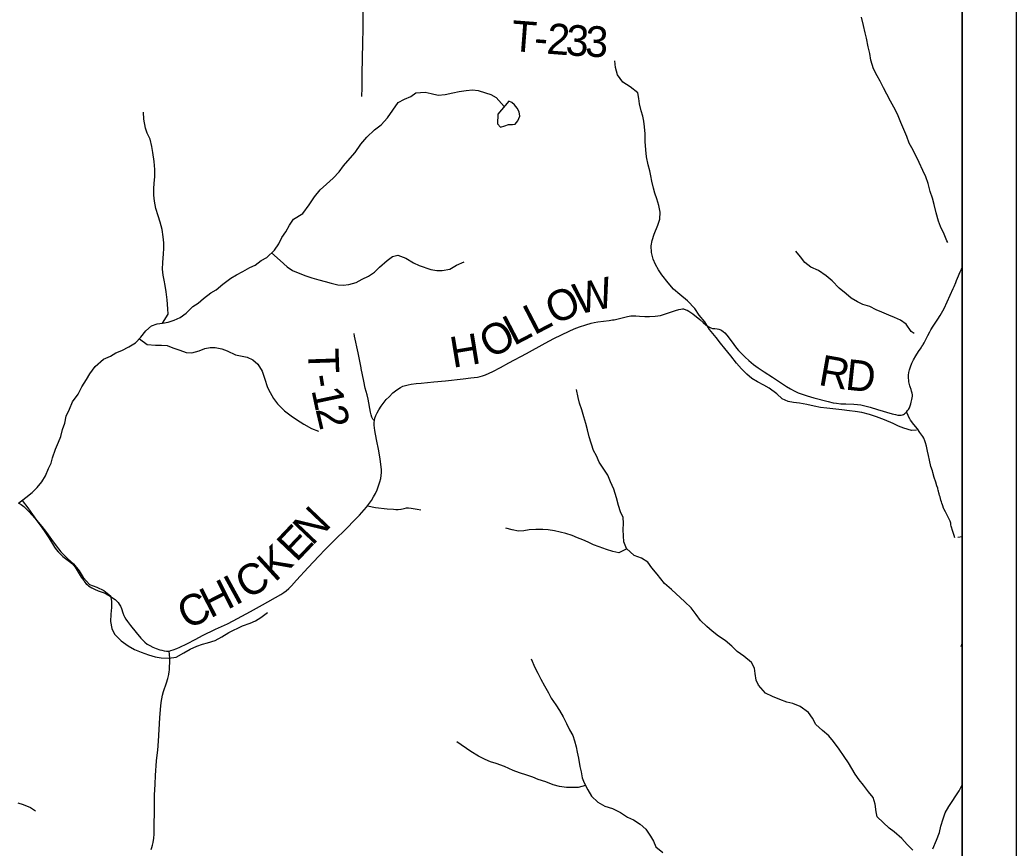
# Model space of a CAD drawing. Extents: x 0 to 34, y 0 to 22.
# Drawn here: x 7.37 to 9.214, y 18.618 to 20.151 of the extents above; entities that cross this region are included whole.
import ezdxf

# ---------------------------------------------------------------- set-up
doc = ezdxf.new("R2010")
doc.units = 0
for name, color, linetype in [('Default', 7, 'Continuous'), ('GM_X_County_Road', 7, 'Continuous'), ('GM_X_County_Road_Text', 7, 'Continuous'), ('GM_X_Minor_Lake', 7, 'Continuous'), ('GM_X_Minor_River', 7, 'Continuous'), ('GM_X_Township_Road', 7, 'Continuous'), ('GM_X_Township_Road_Text', 7, 'Continuous'), ('SH_Cut_Line', 7, 'Continuous'), ('SH_Data', 7, 'Continuous')]:
    doc.layers.add(name, color=color, linetype=linetype)

msp = doc.modelspace()

# ---------------------------------------------------------------- linework, layer by layer
at = {"layer": 'Default'}
msp.add_lwpolyline([(9.1142, 17.7402), (9.1142, 20.5497), (8.8095, 20.7701), (8.7304, 20.823), (8.6734, 20.858), (8.6167, 20.8996), (2.3571, 20.8996)], dxfattribs=at)
at = {"layer": 'GM_X_County_Road'}
for points in [[(9.0115, 19.4251), (9.0134, 19.4277), (9.0153, 19.43), (9.0169, 19.4329), (9.0184, 19.4365), (9.0194, 19.4402), (9.0203, 19.4434), (9.0214, 19.448), (9.022, 19.4516), (9.0224, 19.4546), (9.0224, 19.4571), (9.0219, 19.4602), (9.0208, 19.4637), (9.0197, 19.4666), (9.0184, 19.4715), (9.0176, 19.4738), (9.0163, 19.4786), (9.0159, 19.4811), (9.0158, 19.4817), (9.0155, 19.4835), (9.0151, 19.4885), (9.0152, 19.4934), (9.0158, 19.4983), (9.0169, 19.5031), (9.0188, 19.5089), (9.0213, 19.5152), (9.0246, 19.5219), (9.0285, 19.529), (9.0335, 19.5368), (9.0384, 19.544), (9.0394, 19.5455), (9.04, 19.5466), (9.0413, 19.5487), (9.0422, 19.5503), (9.0438, 19.553), (9.0507, 19.5669), (9.0543, 19.5734), (9.0565, 19.5772), (9.0608, 19.584), (9.0694, 19.597), (9.0737, 19.6038), (9.0762, 19.6081), (9.0808, 19.6169), (9.0867, 19.6292), (9.0979, 19.6535), (9.0995, 19.6575), (9.1026, 19.665), (9.104, 19.6684), (9.1056, 19.6725), (9.1105, 19.6845), (9.1129, 19.6895), (9.1137, 19.6912), (9.1142, 19.6923)], [(8.2051, 19.4882), (8.2169, 19.4897), (8.2218, 19.4906), (8.2266, 19.4919), (8.2318, 19.4937), (8.2387, 19.4967), (8.2454, 19.5), (8.2596, 19.5075), (8.2754, 19.5161), (8.3077, 19.5335), (8.3425, 19.5526), (8.3584, 19.5611), (8.3869, 19.575), (8.396, 19.579), (8.4059, 19.5827), (8.4176, 19.5866), (8.4277, 19.5896), (8.4332, 19.5909), (8.4399, 19.5919), (8.4608, 19.5944), (8.4669, 19.5954), (8.47, 19.596), (8.4851, 19.5995), (8.4902, 19.6009), (8.4925, 19.6015), (8.4949, 19.602), (8.4981, 19.6025), (8.5008, 19.6029), (8.5101, 19.6031), (8.5171, 19.6026), (8.5269, 19.602), (8.5356, 19.6019), (8.5461, 19.6023), (8.551, 19.6028), (8.5558, 19.6038), (8.5618, 19.6055), (8.5835, 19.613), (8.59, 19.615), (8.5936, 19.6157), (8.5967, 19.6159), (8.5986, 19.6158), (8.6026, 19.6145), (8.6054, 19.6133), (8.6086, 19.6115), (8.6157, 19.6065), (8.6288, 19.5961), (8.635, 19.5909), (8.64, 19.5864), (8.6439, 19.5834), (8.6466, 19.5819), (8.6494, 19.5806), (8.6524, 19.5798), (8.6567, 19.5795), (8.661, 19.5792), (8.664, 19.5786), (8.6675, 19.5772), (8.6696, 19.5761), (8.6721, 19.5742), (8.6749, 19.5717), (8.6786, 19.5675), (8.6865, 19.5571), (8.6968, 19.5431), (8.7004, 19.5388), (8.7063, 19.5325), (8.7125, 19.5264), (8.7195, 19.5202), (8.7282, 19.5132), (8.7366, 19.5069), (8.7479, 19.4992), (8.7631, 19.4894), (8.7891, 19.4724), (8.7965, 19.468), (8.8037, 19.4642), (8.811, 19.4609), (8.8185, 19.4579), (8.8274, 19.455), (8.8399, 19.4515), (8.8664, 19.4445), (8.8754, 19.4424), (8.882, 19.4413), (8.89, 19.4405), (8.8992, 19.4401), (8.914, 19.4396), (8.9207, 19.439), (8.9268, 19.4382), (8.9341, 19.4367), (8.9443, 19.4341), (8.9579, 19.43), (8.9846, 19.4217), (8.9907, 19.4202), (8.9956, 19.4193), (8.9993, 19.419), (9.0017, 19.4192), (9.0041, 19.4197), (9.0058, 19.4204), (9.0078, 19.4218), (9.0098, 19.4233), (9.0115, 19.4251)], [(8.0263, 19.409), (8.0274, 19.4138), (8.029, 19.4185), (8.0313, 19.4236), (8.0343, 19.429), (8.0388, 19.4358), (8.0443, 19.4433), (8.0482, 19.4481), (8.0534, 19.4535), (8.0605, 19.4603), (8.0653, 19.4644), (8.0698, 19.4676), (8.0746, 19.4705), (8.079, 19.4727), (8.0837, 19.4744), (8.0885, 19.4757), (8.0946, 19.4768), (8.1039, 19.4778), (8.1126, 19.4786), (8.1361, 19.4808), (8.1577, 19.4828), (8.1904, 19.4864), (8.2051, 19.4882)], [(8.0136, 19.2512), (8.0209, 19.2616), (8.0247, 19.2679), (8.0282, 19.2745), (8.0313, 19.2813), (8.034, 19.2883), (8.0364, 19.296), (8.0379, 19.302), (8.0389, 19.3075), (8.0394, 19.3131), (8.0395, 19.318), (8.0391, 19.3236), (8.0372, 19.3378), (8.0345, 19.3531), (8.0303, 19.3744), (8.0271, 19.3911), (8.0263, 19.3961), (8.026, 19.4007), (8.0258, 19.4037), (8.026, 19.4065), (8.0263, 19.409)], [(7.3666, 19.2573), (7.3721, 19.2541), (7.3772, 19.2504), (7.3819, 19.2462), (7.3852, 19.2425), (7.3872, 19.2401), (7.3974, 19.2285), (7.4052, 19.2189), (7.4108, 19.2115), (7.4174, 19.2018), (7.4234, 19.1924), (7.434, 19.1749), (7.4371, 19.1704), (7.4407, 19.1662), (7.445, 19.1619), (7.4496, 19.1579), (7.4618, 19.1485), (7.4671, 19.144), (7.4697, 19.1412), (7.4724, 19.1377), (7.4835, 19.1197), (7.4881, 19.1132), (7.4898, 19.1109), (7.4929, 19.1074), (7.4949, 19.1055), (7.4973, 19.1036), (7.5032, 19.0996), (7.5084, 19.097), (7.5148, 19.0942), (7.5259, 19.0903), (7.5299, 19.0885), (7.537, 19.0845), (7.5417, 19.0814), (7.5463, 19.0781), (7.5491, 19.0756), (7.5517, 19.0728), (7.554, 19.0697), (7.5561, 19.0658), (7.5582, 19.0612), (7.5608, 19.0535), (7.5627, 19.0483), (7.5637, 19.0461), (7.566, 19.0418), (7.5691, 19.0373), (7.5748, 19.03), (7.5853, 19.0169), (7.5939, 19.0064), (7.5973, 19.0028), (7.6014, 18.9991), (7.6058, 18.9958), (7.6105, 18.9929), (7.6159, 18.9901), (7.6221, 18.9875), (7.6291, 18.9851), (7.6327, 18.9841), (7.6371, 18.9832), (7.6412, 18.9826), (7.6441, 18.9825), (7.6464, 18.9827)], [(7.6464, 18.9827), (7.6494, 18.9836), (7.6537, 18.9852), (7.6604, 18.9877), (7.6662, 18.9899), (7.679, 18.9961), (7.6956, 19.0047), (7.7083, 19.0113), (7.7322, 19.023), (7.7542, 19.0333), (7.7647, 19.0386), (7.7969, 19.0558), (7.8191, 19.0683), (7.853, 19.0876), (7.8588, 19.0913), (7.8628, 19.0942), (7.8679, 19.0987), (7.8726, 19.1036), (7.8818, 19.1137), (7.9037, 19.1374), (7.9232, 19.1583), (7.9353, 19.1707), (7.9493, 19.1847), (7.9773, 19.2121), (7.9872, 19.2223), (7.9987, 19.2345), (8.0119, 19.2493), (8.0136, 19.2512)]]:
    msp.add_lwpolyline(points, dxfattribs=at)
at = {"layer": 'GM_X_Minor_Lake'}
for points in [[(8.2545, 19.9763), (8.2543, 19.9585), (8.2599, 19.9523), (8.2675, 19.9545), (8.2743, 19.9571), (8.2819, 19.9574), (8.2872, 19.958), (8.2919, 19.9637), (8.2954, 19.9727), (8.294, 19.9803), (8.2903, 19.9872), (8.2858, 19.9933), (8.2805, 19.998), (8.2753, 20.0003)], [(8.2753, 20.0003), (8.2545, 19.9763)]]:
    msp.add_lwpolyline(points, dxfattribs=at)
at = {"layer": 'GM_X_Minor_River'}
for p, q in [((9.1065, 19.1932), (9.1142, 19.1945)), ((9.1125, 18.991), (9.1142, 18.9968))]:
    msp.add_line(p, q, dxfattribs=at)
for points in [[(9.088, 19.7388), (9.086, 19.7419), (9.0808, 19.7541), (9.0746, 19.7686), (9.0705, 19.7781), (9.0665, 19.7934), (9.0626, 19.809), (9.0593, 19.8208), (9.0553, 19.833), (9.0513, 19.8478), (9.0469, 19.8604), (9.0414, 19.8722), (9.0347, 19.8867), (9.0236, 19.9096), (9.0166, 19.9226), (9.0122, 19.9348), (9.0063, 19.9481), (9.0008, 19.9611), (8.9949, 19.976), (8.9879, 19.989), (8.9816, 20.0004), (8.9749, 20.0134), (8.9686, 20.0249), (8.9627, 20.0371), (8.9568, 20.0474), (8.9505, 20.0604), (8.9454, 20.0764), (8.9433, 20.0885), (8.9404, 20.1011), (8.9372, 20.1167), (8.9346, 20.1269), (8.9318, 20.1403), (8.9278, 20.1559)], [(9.0299, 19.3915), (9.0205, 19.3908), (9.0065, 19.3952), (8.9967, 19.3991), (8.9869, 19.4038), (8.9707, 19.4108), (8.9556, 19.4163), (8.9428, 19.4207), (8.9284, 19.4243), (8.9163, 19.4263), (8.9057, 19.4276), (8.8917, 19.4289), (8.8751, 19.4307), (8.8637, 19.432), (8.8523, 19.4336), (8.8402, 19.4361), (8.827, 19.4389), (8.813, 19.4417), (8.8024, 19.443), (8.7926, 19.4447), (8.7809, 19.4494), (8.7711, 19.4586), (8.7573, 19.469), (8.7475, 19.4745), (8.7354, 19.4811), (8.7253, 19.4869), (8.7155, 19.4954), (8.7061, 19.505), (8.6964, 19.5157), (8.6864, 19.5291), (8.6748, 19.5426), (8.6669, 19.5525), (8.6591, 19.5629), (8.6468, 19.5778), (8.6379, 19.592), (8.6278, 19.6046), (8.6192, 19.6165), (8.6061, 19.6311), (8.5919, 19.6423), (8.5799, 19.6527), (8.5701, 19.6642), (8.5582, 19.6787), (8.5523, 19.6883), (8.5467, 19.6979), (8.5423, 19.7082), (8.539, 19.72), (8.5388, 19.7328), (8.5404, 19.7427), (8.5444, 19.7544), (8.551, 19.771), (8.5546, 19.7819), (8.5551, 19.7952), (8.5526, 19.807), (8.549, 19.8199), (8.5457, 19.8298), (8.5432, 19.8394), (8.5399, 19.8523), (8.5381, 19.8622), (8.536, 19.8717), (8.5331, 19.8827), (8.5303, 19.8976), (8.5285, 19.9101), (8.5276, 19.9257), (8.5274, 19.9397), (8.5264, 19.953), (8.525, 19.9632), (8.5232, 19.9727), (8.5203, 19.9823), (8.5171, 19.9956), (8.5161, 20.0054), (8.5139, 20.0157), (8.4997, 20.0269), (8.4865, 20.0358), (8.4764, 20.0488), (8.4724, 20.0629), (8.4711, 20.0747)], [(7.6343, 19.5898), (7.6445, 19.5912), (7.6556, 19.5948), (7.6666, 19.6), (7.6777, 19.6082), (7.6904, 19.6201), (7.7003, 19.6268), (7.7099, 19.635), (7.7233, 19.6455), (7.7336, 19.6514), (7.7459, 19.6619), (7.7605, 19.673), (7.7708, 19.679), (7.7826, 19.6849), (7.7956, 19.6927), (7.8055, 19.6971), (7.8166, 19.7053), (7.8269, 19.7108), (7.8411, 19.7247), (7.8496, 19.7363), (7.855, 19.748), (7.8624, 19.7585), (7.8694, 19.7709), (7.8767, 19.7822), (7.8935, 19.7926), (7.9055, 19.8084), (7.9151, 19.8234), (7.9259, 19.8362), (7.9378, 19.8466), (7.9497, 19.8579), (7.9612, 19.8698), (7.9689, 19.8804), (7.977, 19.8901), (7.9905, 19.9051), (8.0013, 19.9205), (8.0124, 19.9336), (8.0263, 19.9471), (8.0389, 19.9568), (8.0504, 19.9695), (8.0605, 19.9834), (8.0705, 19.9981), (8.0823, 20.004), (8.0938, 20.0088), (8.1033, 20.0159), (8.1204, 20.0168), (8.1314, 20.0143), (8.1442, 20.0115), (8.1571, 20.0125), (8.1716, 20.0157), (8.1834, 20.0182), (8.1963, 20.0203), (8.2077, 20.0213), (8.2186, 20.02), (8.2319, 20.016), (8.2417, 20.0125), (8.2515, 20.0071), (8.2667, 19.9904)], [(7.6343, 19.5898), (7.6447, 19.6063), (7.6437, 19.6162), (7.6424, 19.6329), (7.6407, 19.6473), (7.639, 19.6591), (7.6368, 19.669), (7.635, 19.6785), (7.634, 19.6895), (7.6346, 19.7017), (7.6359, 19.7176), (7.6364, 19.7278), (7.6362, 19.7384), (7.6352, 19.7494), (7.6334, 19.7627), (7.6298, 19.7764), (7.6258, 19.7882), (7.6214, 19.802), (7.6189, 19.8153), (7.6179, 19.8266), (7.6181, 19.8384), (7.6186, 19.8483), (7.6199, 19.8604), (7.6201, 19.874), (7.6187, 19.8888), (7.6159, 19.9052), (7.6142, 19.9166), (7.6109, 19.9299), (7.6054, 19.941), (7.6025, 19.9505), (7.5993, 19.9672), (7.5987, 19.9801)], [(7.8359, 19.7196), (7.8519, 19.7056), (7.8646, 19.694), (7.8747, 19.6871), (7.8883, 19.6816), (7.8996, 19.6772), (7.9102, 19.6737), (7.9234, 19.6697), (7.9352, 19.6669), (7.9461, 19.6634), (7.9586, 19.6605), (7.9684, 19.66), (7.9787, 19.661), (7.9924, 19.665), (8.0038, 19.6709), (8.0153, 19.6768), (8.0264, 19.6839), (8.0359, 19.6929), (8.0501, 19.7052), (8.0601, 19.7127), (8.0696, 19.7152), (8.0843, 19.7101), (8.0986, 19.7011), (8.1092, 19.6965), (8.1307, 19.689), (8.1416, 19.6869), (8.1515, 19.6872), (8.1659, 19.6896), (8.1782, 19.6971), (8.1923, 19.7033)], [(9.0254, 19.5707), (9.0198, 19.5744), (9.0105, 19.5874), (9, 19.5951), (8.9894, 19.6002), (8.9785, 19.6045), (8.966, 19.61), (8.9555, 19.6143), (8.9434, 19.6202), (8.9306, 19.6241), (8.9204, 19.6292), (8.9091, 19.6358), (8.8994, 19.6435), (8.887, 19.6543), (8.8739, 19.6681), (8.8626, 19.677), (8.8483, 19.6867), (8.8344, 19.6929), (8.8231, 19.7018), (8.8149, 19.7121), (8.8063, 19.7225)], [(7.3677, 19.2562), (7.3811, 19.2667), (7.3926, 19.2764), (7.4022, 19.2853), (7.4107, 19.2958), (7.4177, 19.3067), (7.4231, 19.3203), (7.4278, 19.3305), (7.4306, 19.3403), (7.4361, 19.3566), (7.4416, 19.369), (7.4455, 19.3799), (7.4491, 19.3928), (7.453, 19.4045), (7.4558, 19.4177), (7.4621, 19.4305), (7.4672, 19.4437), (7.478, 19.4584), (7.4849, 19.4716), (7.4935, 19.4851), (7.4997, 19.496), (7.5093, 19.5092), (7.525, 19.523), (7.5376, 19.5285), (7.5479, 19.5344), (7.5586, 19.5388), (7.5716, 19.5455), (7.5838, 19.5533), (7.5938, 19.5634), (7.6034, 19.5754), (7.6134, 19.5844), (7.624, 19.588), (7.6343, 19.5898)], [(7.5912, 19.5607), (7.6057, 19.5503), (7.6209, 19.549), (7.6319, 19.5489), (7.6425, 19.548), (7.6534, 19.544), (7.6659, 19.5393), (7.6776, 19.5353), (7.6882, 19.5344), (7.7019, 19.5384), (7.7122, 19.5425), (7.7221, 19.5446), (7.7315, 19.5445), (7.744, 19.542), (7.7538, 19.5385), (7.7689, 19.5307), (7.7787, 19.5291), (7.7905, 19.5266), (7.801, 19.5219), (7.8108, 19.5138), (7.8186, 19.5005), (7.8229, 19.4875), (7.8284, 19.4707), (7.8336, 19.4612), (7.8395, 19.4501), (7.8466, 19.4405), (7.8601, 19.4271), (7.8721, 19.4178), (7.8819, 19.4112), (7.8958, 19.4027), (7.9101, 19.3949), (7.9226, 19.3899)], [(9.0229, 18.6145), (9.0124, 18.6249), (9.003, 18.6356), (8.9888, 18.6483), (8.979, 18.6553), (8.9682, 18.6653), (8.9573, 18.676), (8.9551, 18.6855), (8.9534, 18.6992), (8.9498, 18.7118), (8.9412, 18.7221), (8.9315, 18.7348), (8.9237, 18.7447), (8.9162, 18.7547), (8.904, 18.7757), (8.8961, 18.7876), (8.8865, 18.801), (8.876, 18.8155), (8.8678, 18.8259), (8.8558, 18.8355), (8.8434, 18.8471), (8.8375, 18.8585), (8.8301, 18.8692), (8.8143, 18.8804), (8.8007, 18.8855), (8.7897, 18.8883), (8.7769, 18.8934), (8.7633, 18.8986), (8.7501, 18.9048), (8.7374, 18.9194), (8.733, 18.9289), (8.7309, 18.9415), (8.7299, 18.951), (8.7247, 18.9613), (8.7104, 18.9732), (8.698, 18.9821), (8.6879, 18.9921), (8.6755, 19.0021), (8.6635, 19.0106), (8.6519, 19.0195), (8.6418, 19.0284), (8.6301, 19.0391), (8.6219, 19.0502), (8.6126, 19.0625), (8.601, 19.0736), (8.5766, 19.0967), (8.5635, 19.1075), (8.5497, 19.1251), (8.54, 19.137), (8.5325, 19.1474), (8.5205, 19.1544), (8.5073, 19.1595), (8.4927, 19.1725), (8.4879, 19.1847), (8.4867, 19.2068), (8.4872, 19.2193), (8.4866, 19.2299), (8.4822, 19.2406), (8.4785, 19.252), (8.4745, 19.2665), (8.4694, 19.2825), (8.4631, 19.2962), (8.4584, 19.308), (8.4498, 19.3214), (8.4427, 19.3325), (8.4372, 19.3439), (8.432, 19.3539), (8.424, 19.379), (8.4208, 19.3923), (8.4179, 19.4041), (8.4142, 19.4159), (8.4102, 19.4293), (8.4062, 19.4414), (8.4037, 19.4517), (8.4005, 19.4666)], [(7.3744, 19.2614), (7.3847, 19.2476), (7.3933, 19.2354), (7.4007, 19.2247), (7.4104, 19.2135), (7.4194, 19.202), (7.4283, 19.1894), (7.435, 19.1798), (7.4458, 19.1664), (7.4589, 19.1537), (7.4694, 19.1441), (7.4795, 19.1314), (7.4873, 19.1188), (7.4989, 19.1058), (7.5125, 19.101), (7.5257, 19.0948), (7.5377, 19.0848), (7.5398, 19.0749), (7.5393, 19.0631), (7.5384, 19.051), (7.5375, 19.0374), (7.54, 19.0244), (7.5451, 19.0137), (7.5575, 19.0014), (7.5706, 18.9922), (7.5819, 18.9859), (7.5944, 18.9805), (7.608, 18.9757), (7.6204, 18.9722), (7.6314, 18.9705), (7.6458, 18.9695), (7.6591, 18.9716), (7.6736, 18.9794), (7.6851, 18.9865), (7.6976, 18.992), (7.7079, 18.9956), (7.7174, 18.9978), (7.7315, 19.0021), (7.7437, 19.0088), (7.7571, 19.017), (7.7823, 19.0292), (7.7964, 19.0343), (7.8063, 19.0387), (7.8162, 19.0446), (7.8281, 19.0543)], [(8.4935, 19.1718), (8.4789, 19.1648), (8.468, 19.1672), (8.4559, 19.1704), (8.4423, 19.1759), (8.4321, 19.1794), (8.4219, 19.1841), (8.4121, 19.1888), (8.4023, 19.1923), (8.3925, 19.1966), (8.3808, 19.2002), (8.3702, 19.203), (8.36, 19.205), (8.3479, 19.2071), (8.3384, 19.2076), (8.3252, 19.2078), (8.3126, 19.2068), (8.3031, 19.2054), (8.2933, 19.2048), (8.2812, 19.2068), (8.2695, 19.2104)], [(8.3165, 18.9682), (8.3235, 18.9525), (8.3286, 18.9419), (8.3342, 18.9308), (8.3409, 18.9182), (8.3483, 18.9052), (8.3535, 18.8956), (8.362, 18.8834), (8.3687, 18.8727), (8.3758, 18.8612), (8.3817, 18.8486), (8.3876, 18.8372), (8.3939, 18.8265), (8.3968, 18.8169), (8.4001, 18.8055), (8.4019, 18.7956), (8.404, 18.7846), (8.4068, 18.769), (8.409, 18.7595), (8.4111, 18.7481), (8.4144, 18.7386), (8.4215, 18.726), (8.4285, 18.7141), (8.4401, 18.7033), (8.4529, 18.696), (8.4669, 18.6912), (8.4816, 18.6838), (8.4951, 18.6753), (8.5061, 18.6702), (8.5181, 18.6621), (8.529, 18.6529), (8.5375, 18.6402), (8.5427, 18.6307), (8.5475, 18.6204), (8.5603, 18.61)], [(8.417, 18.7339), (8.4033, 18.73), (8.3938, 18.7305), (8.3821, 18.7303), (8.3688, 18.732), (8.3575, 18.7352), (8.3439, 18.741), (8.3296, 18.745), (8.3194, 18.7493), (8.3084, 18.7529), (8.2948, 18.7572), (8.2832, 18.7619), (8.2673, 18.769), (8.2515, 18.7745), (8.2413, 18.7777), (8.2315, 18.782), (8.219, 18.7882), (8.2047, 18.7967), (8.1788, 18.8145)], [(9.0604, 18.6166), (9.0667, 18.6325), (9.0722, 18.6468), (9.075, 18.6589), (9.0793, 18.6725), (9.0829, 18.6835), (9.0899, 18.6951), (9.1088, 18.7241), (9.1142, 18.7354)], [(7.3661, 18.7018), (7.3762, 18.6986), (7.3895, 18.6935), (7.3992, 18.6869)]]:
    msp.add_lwpolyline(points, dxfattribs=at)
at = {"layer": 'GM_X_Township_Road'}
for points in [[(8.0033, 20.009), (8.0034, 20.0252), (8.0035, 20.0518), (8.0042, 20.0792), (8.0047, 20.1084), (8.0052, 20.1345), (8.0056, 20.1693), (8.0061, 20.2014), (8.0062, 20.2147)], [(8.0015, 19.5071), (7.9997, 19.5162), (7.996, 19.5344), (7.9897, 19.5654), (7.9889, 19.5703)], [(8.0263, 19.409), (8.0232, 19.4121), (8.0216, 19.4156), (8.0204, 19.4199), (8.0193, 19.4249), (8.0147, 19.449), (8.0126, 19.4567), (8.0093, 19.4694), (8.0065, 19.4821), (8.0017, 19.5058), (8.0015, 19.5071)], [(9.101, 19.1924), (9.0996, 19.1966), (9.0963, 19.2059), (9.0946, 19.2118), (9.0941, 19.2136), (9.0936, 19.2166), (9.0934, 19.2177), (9.0932, 19.2195), (9.0927, 19.2212), (9.092, 19.2229), (9.0838, 19.2402), (9.0806, 19.2462), (9.0801, 19.2473), (9.0784, 19.2517), (9.0778, 19.2533), (9.0766, 19.2566), (9.076, 19.2589), (9.0751, 19.2617), (9.0734, 19.268), (9.0727, 19.2707), (9.0719, 19.274), (9.0714, 19.2755), (9.0707, 19.2787), (9.0702, 19.2802), (9.0695, 19.2828), (9.0691, 19.2844), (9.0677, 19.2887), (9.0654, 19.2952), (9.0626, 19.3039), (9.0601, 19.3132), (9.0592, 19.316), (9.0567, 19.3242), (9.0537, 19.3357), (9.0518, 19.3448), (9.0501, 19.3526), (9.0482, 19.3619), (9.0467, 19.3679), (9.0454, 19.372), (9.0434, 19.3765), (9.0415, 19.3797), (9.0363, 19.3873), (9.0316, 19.3939), (9.025, 19.402), (9.0189, 19.4098), (9.0173, 19.4124), (9.0153, 19.4167), (9.0138, 19.4203), (9.0115, 19.4251)], [(8.0136, 19.2512), (8.0282, 19.2486), (8.0497, 19.246), (8.0614, 19.2451), (8.0657, 19.2449), (8.07, 19.2449), (8.0755, 19.2455), (8.0761, 19.2454), (8.0815, 19.2466), (8.0858, 19.2475), (8.0894, 19.2477), (8.0944, 19.2474), (8.1054, 19.2454), (8.1121, 19.2443)], [(7.6129, 18.6155), (7.6143, 18.619), (7.6157, 18.6237), (7.6167, 18.6285), (7.6179, 18.6365), (7.6186, 18.644), (7.6188, 18.6514), (7.6188, 18.6719), (7.6189, 18.675), (7.6191, 18.6843), (7.619, 18.7015), (7.6189, 18.7077), (7.6191, 18.7133), (7.6193, 18.7158), (7.6202, 18.7362), (7.6211, 18.7524), (7.6231, 18.7795), (7.6242, 18.79), (7.6251, 18.7993), (7.6264, 18.8159), (7.629, 18.859), (7.6304, 18.8744), (7.6318, 18.8873), (7.6328, 18.8946), (7.6342, 18.9012), (7.636, 18.9077), (7.6413, 18.9241), (7.6436, 18.9318), (7.6455, 18.9396), (7.6465, 18.9451), (7.6468, 18.9476), (7.647, 18.95), (7.647, 18.9537), (7.6473, 18.9617), (7.6473, 18.9698), (7.647, 18.9763), (7.6464, 18.9827)]]:
    msp.add_lwpolyline(points, dxfattribs=at)
at = {"layer": 'SH_Cut_Line'}
msp.add_lwpolyline([(9.1142, 14.0996), (9.1142, 20.8996), (2.3142, 20.8996)], dxfattribs=at)
at = {"layer": 'SH_Data'}
for p, q in [((9.2142, 20.9996), (9.2142, 13.9996)), ((9.1142, 20.8996), (9.1142, 14.0996))]:
    msp.add_line(p, q, dxfattribs=at)

# ---------------------------------------------------------------- texts
at = {"layer": 'GM_X_County_Road_Text'}
for s, rotation, p in [('W', 12.523, (8.4019, 19.6051)), ('O', 23.8108, (8.3589, 19.5859)), ('L', 27.4966, (8.3221, 19.5667)), ('L', 27.5311, (8.2844, 19.547)), ('O', 30.0251, (8.2417, 19.5223)), ('H', 9.3599, (8.1714, 19.5067)), ('R', 350.0147, (8.8465, 19.4755)), ('D', 353.9406, (8.8966, 19.4668)), ('N', 46.3177, (7.9112, 19.1765)), ('E', 46.4451, (7.8819, 19.1457)), ('K', 42.5846, (7.8421, 19.1089)), ('C', 29.1138, (7.7895, 19.0777)), ('H', 26.8904, (7.7224, 19.0427)), ('I', 28.7352, (7.7687, 19.0663)), ('C', 25.859, (7.6794, 19.0219))]:
    msp.add_text(s, height=0.0568, rotation=rotation, dxfattribs=at).set_placement(p)
at = {"layer": 'GM_X_Township_Road_Text'}
for s, rotation, p in [('T', 355.5858, (8.2782, 20.0935)), ('2', 355.6583, (8.3439, 20.0884)), ('3', 355.9059, (8.3791, 20.0857)), ('3', 357.3557, (8.4156, 20.0832)), ('-', 355.6002, (8.3206, 20.0902)), ('T', 271.8903, (7.9031, 19.5421)), ('-', 279.166, (7.9052, 19.4918)), ('1', 281.9695, (7.9095, 19.4658)), ('2', 283.1972, (7.9171, 19.4303))]:
    msp.add_text(s, height=0.0568, rotation=rotation, dxfattribs=at).set_placement(p)

doc.saveas('drawing.dxf')
